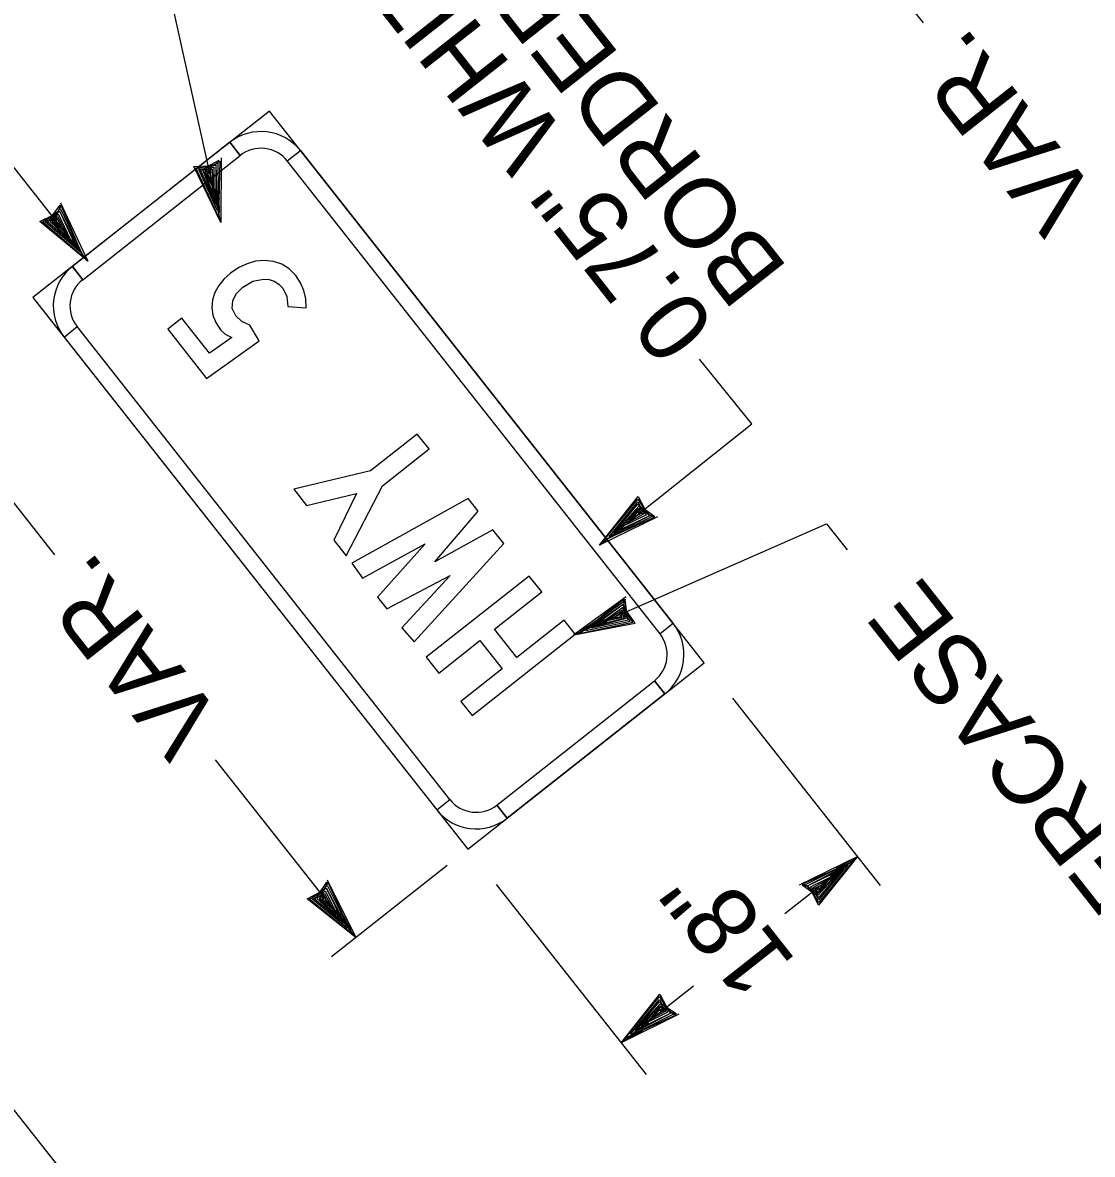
# Model space of a CAD drawing. Extents: x 671946 to 673995, y 1673066 to 1674936.
# Drawn here: x 672428.5 to 672492.5, y 1673764.1 to 1673831.7 of the extents above; entities that cross this region are included whole.
import ezdxf

# ---------------------------------------------------------------- set-up
doc = ezdxf.new("R2010")
doc.units = 0
for name, color, linetype in [('C-ANNO-SYMB', 7, 'Continuous'), ('Level 1', 7, 'Continuous'), ('V-SIGNAL-LOOP', 7, 'Continuous')]:
    doc.layers.add(name, color=color, linetype=linetype)

msp = doc.modelspace()

# ---------------------------------------------------------------- linework, layer by layer
at = {"layer": 'C-ANNO-SYMB'}
for p, q in [((672443.297, 1673826.427), (672429.161, 1673815.283)), ((672469.299, 1673793.444), (672443.297, 1673826.427)), ((672440.941, 1673824.57), (672431.517, 1673817.141)), ((672440.941, 1673824.57), (672441.56, 1673823.785)), ((672441.56, 1673823.785), (672440.941, 1673824.57)), ((672432.136, 1673816.355), (672441.56, 1673823.785)), ((672441.56, 1673823.785), (672441.56, 1673823.785)), ((672441.56, 1673823.785), (672441.56, 1673823.785)), ((672444.369, 1673823.452), (672445.154, 1673824.071)), ((672444.369, 1673823.452), (672445.154, 1673824.071)), ((672444.369, 1673823.452), (672445.154, 1673824.071)), ((672445.154, 1673824.071), (672467.442, 1673795.8)), ((672466.657, 1673795.181), (672444.369, 1673823.452)), ((672432.136, 1673816.355), (672431.517, 1673817.141)), ((672431.517, 1673817.141), (672432.136, 1673816.355)), ((672429.161, 1673815.283), (672455.164, 1673782.3)), ((672431.019, 1673812.928), (672431.804, 1673813.547)), ((672431.019, 1673812.928), (672431.804, 1673813.547)), ((672431.804, 1673813.547), (672431.804, 1673813.547)), ((672431.804, 1673813.547), (672431.804, 1673813.547)), ((672454.092, 1673785.275), (672431.804, 1673813.547)), ((672431.019, 1673812.928), (672453.306, 1673784.656)), ((672467.442, 1673795.8), (672466.657, 1673795.181)), ((672467.442, 1673795.8), (672466.657, 1673795.181)), ((672466.657, 1673795.181), (672466.657, 1673795.181)), ((672466.657, 1673795.181), (672466.657, 1673795.181)), ((672455.164, 1673782.3), (672469.299, 1673793.444)), ((672469.299, 1673793.444), (672469.299, 1673793.444)), ((672469.299, 1673793.444), (672469.299, 1673793.444)), ((672456.9, 1673784.943), (672466.324, 1673792.372)), ((672466.324, 1673792.372), (672466.943, 1673791.587)), ((672466.943, 1673791.587), (672466.324, 1673792.372)), ((672466.943, 1673791.587), (672457.52, 1673784.158)), ((672453.306, 1673784.656), (672454.092, 1673785.275)), ((672453.306, 1673784.656), (672454.092, 1673785.275)), ((672457.52, 1673784.158), (672456.9, 1673784.943)), ((672456.9, 1673784.943), (672456.9, 1673784.943)), ((672456.9, 1673784.943), (672456.9, 1673784.943)), ((672456.9, 1673784.943), (672457.52, 1673784.158)), ((672457.52, 1673784.158), (672456.9, 1673784.943))]:
    msp.add_line(p, q, dxfattribs=at)
for points in [[(672469.462, 1673714.173), (672348.811, 1673867.215), (672334.833, 1673856.196), (672455.485, 1673703.154)], [(672445.506, 1673814.671), (672445.473, 1673815.211), (672445.355, 1673815.711), (672445.155, 1673816.172), (672444.873, 1673816.599), (672444.487, 1673816.999), (672444.048, 1673817.283), (672443.554, 1673817.451), (672443.002, 1673817.502), (672442.478, 1673817.453), (672441.966, 1673817.31), (672441.469, 1673817.075), (672440.982, 1673816.745), (672440.584, 1673816.385), (672440.269, 1673815.999), (672440.043, 1673815.592), (672439.903, 1673815.159), (672439.861, 1673814.692), (672439.922, 1673814.238), (672440.096, 1673813.793), (672440.373, 1673813.364), (672440.66, 1673813.1), (672441.059, 1673812.897), (672439.722, 1673811.953), (672438.065, 1673814.054), (672437.22, 1673813.387), (672439.532, 1673810.454), (672442.695, 1673812.705), (672442.133, 1673813.643), (672441.66, 1673813.851), (672441.29, 1673814.188), (672441.076, 1673814.637), (672441.112, 1673815.116), (672441.336, 1673815.524), (672441.714, 1673815.902), (672442.319, 1673816.26), (672442.94, 1673816.394), (672443.279, 1673816.371), (672443.582, 1673816.27), (672443.859, 1673816.094), (672444.101, 1673815.84), (672444.347, 1673815.354), (672444.399, 1673814.756)], [(672445.517, 1673802.862), (672448.518, 1673803.564), (672447.15, 1673800.79), (672447.894, 1673799.847), (672450.054, 1673804.038), (672452.846, 1673806.239), (672452.145, 1673807.128), (672449.353, 1673804.927), (672444.759, 1673803.824)], [(672457.309, 1673800.577), (672456.66, 1673801.4), (672453.191, 1673799.485), (672455.785, 1673802.511), (672455.185, 1673803.271), (672448.234, 1673799.416), (672448.867, 1673798.508), (672452.61, 1673800.571), (672449.769, 1673797.364), (672450.317, 1673796.669), (672454.113, 1673798.664), (672451.214, 1673795.531), (672451.955, 1673794.695)], [(672461.584, 1673795.155), (672460.917, 1673796), (672458.09, 1673793.771), (672456.756, 1673795.463), (672459.584, 1673797.692), (672458.841, 1673798.634), (672452.68, 1673793.776), (672453.422, 1673792.834), (672455.893, 1673794.782), (672457.227, 1673793.091), (672454.756, 1673791.143), (672455.422, 1673790.298)]]:
    msp.add_lwpolyline(points, close=True, dxfattribs=at)
for centre, radius, start, end in [((672442.798, 1673822.214), 3, 38.2506, 128.25081), ((672442.798, 1673822.214), 2, 38.2506, 128.25081), ((672433.375, 1673814.785), 3, 128.25054, 218.25075), ((672433.375, 1673814.785), 2, 128.25054, 218.25075), ((672465.086, 1673793.943), 3, 308.25039, 38.2506), ((672465.086, 1673793.943), 2, 308.25039, 38.2506), ((672455.662, 1673786.514), 2, 218.25075, 308.25039), ((672455.662, 1673786.514), 3, 218.25075, 308.25039)]:
    msp.add_arc(centre, radius, start, end, dxfattribs=at)
at = {"layer": 'Level 1'}
for p, q in [((672482.408, 1673831.709), (672447.972, 1673875.39)), ((672432.439, 1673817.458), (672422.781, 1673829.709)), ((672438.785, 1673823.132), (672439.64, 1673823.153)), ((672440.387, 1673819.773), (672438.785, 1673823.132)), ((672438.911, 1673823.051), (672439.568, 1673823.11)), ((672439.18, 1673822.919), (672440.106, 1673823.226)), ((672439.318, 1673822.897), (672439.975, 1673823.09)), ((672439.355, 1673822.985), (672440.106, 1673823.226)), ((672439.568, 1673823.11), (672440.287, 1673823.507)), ((672439.64, 1673823.153), (672440.024, 1673823.235)), ((672439.975, 1673823.09), (672439.986, 1673821.406)), ((672440.024, 1673823.235), (672440.33, 1673823.436)), ((672440.106, 1673823.226), (672440.102, 1673820.868)), ((672440.106, 1673823.226), (672440.182, 1673820.749)), ((672440.134, 1673823.338), (672440.223, 1673823.303)), ((672440.223, 1673823.303), (672440.26, 1673820.124)), ((672440.33, 1673823.436), (672440.248, 1673820.309)), ((672440.422, 1673823.631), (672440.387, 1673819.773)), ((672440.27, 1673820.072), (672438.911, 1673823.051)), ((672439.061, 1673822.975), (672439.355, 1673822.985)), ((672440.176, 1673820.509), (672439.061, 1673822.975)), ((672440.102, 1673820.868), (672439.18, 1673822.919)), ((672440.182, 1673820.749), (672439.318, 1673822.897)), ((672439.424, 1673822.785), (672439.868, 1673822.962)), ((672439.986, 1673821.406), (672439.424, 1673822.785)), ((672439.846, 1673823.062), (672439.438, 1673822.843)), ((672439.438, 1673822.843), (672439.899, 1673822.056)), ((672439.523, 1673822.697), (672439.777, 1673822.887)), ((672439.913, 1673821.872), (672439.523, 1673822.697)), ((672439.605, 1673822.691), (672439.7, 1673822.736)), ((672439.794, 1673822.303), (672439.605, 1673822.691)), ((672439.7, 1673822.736), (672439.846, 1673823.062)), ((672439.777, 1673822.887), (672439.794, 1673822.303)), ((672439.868, 1673822.962), (672439.913, 1673821.872)), ((672439.899, 1673822.056), (672439.879, 1673821.785)), ((672439.879, 1673821.785), (672440.034, 1673821.307)), ((672440.034, 1673821.307), (672440.037, 1673821.79)), ((672440.291, 1673821.228), (672440.176, 1673820.509)), ((672440.324, 1673820.323), (672440.291, 1673821.228)), ((672430.027, 1673819.81), (672430.74, 1673820.476)), ((672430.159, 1673819.944), (672430.74, 1673820.476)), ((672430.3, 1673820.147), (672430.787, 1673820.807)), ((672430.347, 1673820.215), (672430.662, 1673820.45)), ((672430.662, 1673820.45), (672430.856, 1673820.761)), ((672430.787, 1673820.807), (672430.719, 1673820.59)), ((672430.719, 1673820.59), (672430.814, 1673820.596)), ((672430.74, 1673820.476), (672431.722, 1673818.332)), ((672430.74, 1673820.476), (672431.844, 1673818.258)), ((672430.808, 1673820.954), (672432.439, 1673817.458)), ((672430.814, 1673820.596), (672432.177, 1673817.723)), ((672430.856, 1673820.761), (672432.089, 1673817.886)), ((672429.579, 1673819.839), (672430.347, 1673820.215)), ((672432.439, 1673817.458), (672429.579, 1673819.839)), ((672429.728, 1673819.818), (672430.3, 1673820.147)), ((672432.208, 1673817.68), (672429.728, 1673819.818)), ((672429.896, 1673819.811), (672430.159, 1673819.944)), ((672431.94, 1673818.037), (672429.896, 1673819.811)), ((672431.722, 1673818.332), (672430.027, 1673819.81)), ((672430.162, 1673819.849), (672430.677, 1673820.299)), ((672431.844, 1673818.258), (672430.162, 1673819.849)), ((672430.572, 1673820.219), (672430.294, 1673819.849)), ((672430.294, 1673819.849), (672431.041, 1673819.327)), ((672430.305, 1673819.79), (672430.634, 1673820.137)), ((672431.392, 1673818.773), (672430.305, 1673819.79)), ((672430.431, 1673819.752), (672430.583, 1673820.031)), ((672431.131, 1673819.166), (672430.431, 1673819.752)), ((672430.509, 1673819.781), (672430.576, 1673819.862)), ((672430.843, 1673819.508), (672430.509, 1673819.781)), ((672430.576, 1673819.862), (672430.572, 1673820.219)), ((672430.583, 1673820.031), (672430.843, 1673819.508)), ((672430.634, 1673820.137), (672431.131, 1673819.166)), ((672430.677, 1673820.299), (672431.392, 1673818.773)), ((672431.041, 1673819.327), (672431.136, 1673819.072)), ((672430.479, 1673799.898), (672422.501, 1673810.019)), ((672463.039, 1673800.478), (672465.359, 1673803.388)), ((672463.257, 1673800.714), (672465.34, 1673803.239)), ((672463.608, 1673800.99), (672465.338, 1673803.071)), ((672463.827, 1673801.09), (672465.381, 1673802.806)), ((672463.898, 1673801.213), (672465.339, 1673802.939)), ((672465.338, 1673803.071), (672465.476, 1673802.811)), ((672465.339, 1673802.939), (672466.02, 1673802.241)), ((672465.34, 1673803.239), (672465.682, 1673802.674)), ((672465.359, 1673803.388), (672465.751, 1673802.628)), ((672465.381, 1673802.806), (672465.841, 1673802.3)), ((672465.476, 1673802.811), (672466.02, 1673802.241)), ((672466.499, 1673802.183), (672463.039, 1673800.478)), ((672466.142, 1673802.169), (672463.299, 1673800.745)), ((672466.307, 1673802.131), (672463.459, 1673800.837)), ((672466.02, 1673802.241), (672463.827, 1673801.09)), ((672466.02, 1673802.241), (672463.898, 1673801.213)), ((672464.332, 1673801.553), (672465.325, 1673802.661)), ((672465.841, 1673802.3), (672464.332, 1673801.553)), ((672464.719, 1673801.822), (672465.29, 1673802.534)), ((672465.679, 1673802.339), (672464.719, 1673801.822)), ((672465.384, 1673802.674), (672464.878, 1673801.916)), ((672465.054, 1673802.117), (672465.32, 1673802.457)), ((672465.571, 1673802.389), (672465.054, 1673802.117)), ((672465.29, 1673802.534), (672465.571, 1673802.389)), ((672465.32, 1673802.457), (672465.402, 1673802.392)), ((672465.325, 1673802.661), (672465.679, 1673802.339)), ((672465.76, 1673802.403), (672465.384, 1673802.674)), ((672465.402, 1673802.392), (672465.76, 1673802.403)), ((672465.682, 1673802.674), (672466.352, 1673802.201)), ((672465.751, 1673802.628), (672465.993, 1673802.319)), ((672465.993, 1673802.319), (672466.307, 1673802.131)), ((672466.352, 1673802.201), (672466.133, 1673802.265)), ((672466.133, 1673802.265), (672466.142, 1673802.169)), ((672464.878, 1673801.916), (672464.625, 1673801.815)), ((672464.628, 1673797.388), (672461.509, 1673795.119)), ((672464.449, 1673797.078), (672461.866, 1673795.224)), ((672464.493, 1673797.243), (672462.023, 1673795.323)), ((672464.457, 1673796.937), (672462.417, 1673795.531)), ((672464.457, 1673796.937), (672462.559, 1673795.537)), ((672464.425, 1673796.752), (672463.062, 1673795.763)), ((672464.659, 1673796.108), (672464.425, 1673796.752)), ((672464.53, 1673797.026), (672464.449, 1673797.078)), ((672464.708, 1673796.19), (672464.457, 1673796.937)), ((672464.758, 1673796.01), (672464.457, 1673796.937)), ((672464.513, 1673796.877), (672464.493, 1673797.243)), ((672464.674, 1673796.519), (672464.513, 1673796.877)), ((672464.576, 1673797.25), (672464.53, 1673797.026)), ((672464.682, 1673796.436), (672464.576, 1673797.25)), ((672462.417, 1673795.531), (672464.659, 1673796.108)), ((672462.954, 1673795.743), (672463.341, 1673796.031)), ((672463.062, 1673795.763), (672464.505, 1673796.127)), ((672463.637, 1673796.078), (672463.43, 1673795.9)), ((672464.385, 1673796.589), (672463.48, 1673795.98)), ((672463.48, 1673795.98), (672464.376, 1673796.155)), ((672464.544, 1673796.173), (672463.637, 1673796.078)), ((672464.378, 1673796.471), (672463.898, 1673796.14)), ((672463.898, 1673796.14), (672464.322, 1673796.217)), ((672464.303, 1673796.32), (672464.479, 1673796.631)), ((672464.322, 1673796.217), (672464.303, 1673796.32)), ((672464.376, 1673796.155), (672464.378, 1673796.471)), ((672464.505, 1673796.127), (672464.385, 1673796.589)), ((672464.479, 1673796.631), (672464.544, 1673796.173)), ((672465.164, 1673795.818), (672464.674, 1673796.519)), ((672465.024, 1673795.871), (672464.682, 1673796.436)), ((672464.873, 1673795.947), (672464.708, 1673796.19)), ((672461.509, 1673795.119), (672465.164, 1673795.818)), ((672461.819, 1673795.201), (672465.024, 1673795.871)), ((672461.866, 1673795.224), (672461.989, 1673795.394)), ((672461.989, 1673795.394), (672462.737, 1673795.903)), ((672462.226, 1673795.384), (672464.873, 1673795.947)), ((672462.737, 1673795.903), (672462.226, 1673795.384)), ((672462.559, 1673795.537), (672464.758, 1673796.01)), ((672463.43, 1673795.9), (672462.954, 1673795.743)), ((672462.023, 1673795.323), (672461.819, 1673795.201)), ((672471.001, 1673791.34), (672479.83, 1673780.141)), ((672448.463, 1673777.018), (672440.083, 1673787.647)), ((672474.123, 1673778.454), (672478.463, 1673781.876)), ((672475.001, 1673780.172), (672478.463, 1673781.876)), ((672478.463, 1673781.876), (672476.141, 1673778.967)), ((672453.923, 1673781.322), (672447.018, 1673775.879)), ((672475.193, 1673780.224), (672478.042, 1673781.516)), ((672475.359, 1673780.186), (672478.203, 1673781.608)), ((672475.48, 1673780.114), (672477.675, 1673781.264)), ((672475.48, 1673780.114), (672477.603, 1673781.141)), ((672477.675, 1673781.264), (672476.119, 1673779.549)), ((672478.245, 1673781.64), (672476.159, 1673779.116)), ((672477.603, 1673781.141), (672476.161, 1673779.415)), ((672477.893, 1673781.364), (672476.162, 1673779.284)), ((672477.995, 1673781.579), (672477.196, 1673781.154)), ((672477.196, 1673781.154), (672477.893, 1673781.364)), ((672478.203, 1673781.608), (672477.995, 1673781.579)), ((672478.042, 1673781.516), (672478.245, 1673781.64)), ((672446.759, 1673780.479), (672448.463, 1673777.018)), ((672475.659, 1673780.055), (672477.169, 1673780.801)), ((672475.822, 1673780.016), (672476.782, 1673780.532)), ((672477.169, 1673780.801), (672476.175, 1673779.693)), ((672476.782, 1673780.532), (672476.21, 1673779.821)), ((672476.622, 1673780.439), (672476.876, 1673780.539)), ((672477.237, 1673780.887), (672476.802, 1673780.679)), ((672476.876, 1673780.539), (672477.237, 1673780.887)), ((672446.002, 1673779.32), (672446.701, 1673780)), ((672446.131, 1673779.456), (672446.701, 1673780)), ((672446.136, 1673779.361), (672446.642, 1673779.821)), ((672446.268, 1673779.662), (672446.741, 1673780.332)), ((672446.314, 1673779.731), (672446.623, 1673779.973)), ((672446.623, 1673779.973), (672446.811, 1673780.287)), ((672446.642, 1673779.821), (672447.388, 1673778.311)), ((672446.741, 1673780.332), (672446.677, 1673780.113)), ((672446.677, 1673780.113), (672446.773, 1673780.121)), ((672446.701, 1673780), (672447.728, 1673777.877)), ((672446.701, 1673780), (672447.851, 1673777.806)), ((672446.773, 1673780.121), (672448.195, 1673777.277)), ((672446.811, 1673780.287), (672448.103, 1673777.438)), ((672456.866, 1673780.196), (672465.821, 1673768.836)), ((672475.819, 1673779.681), (672475.148, 1673780.154)), ((672475.148, 1673780.154), (672475.367, 1673780.091)), ((672475.508, 1673780.036), (672475.193, 1673780.224)), ((672475.367, 1673780.091), (672475.359, 1673780.186)), ((672476.024, 1673779.544), (672475.48, 1673780.114)), ((672476.161, 1673779.415), (672475.48, 1673780.114)), ((672475.749, 1673779.727), (672475.508, 1673780.036)), ((672476.119, 1673779.549), (672475.659, 1673780.055)), ((672476.098, 1673779.963), (672475.741, 1673779.952)), ((672475.741, 1673779.952), (672476.116, 1673779.681)), ((672476.175, 1673779.693), (672475.822, 1673780.016)), ((672475.929, 1673779.966), (672476.446, 1673780.237)), ((672476.21, 1673779.821), (672475.929, 1673779.966)), ((672476.18, 1673779.897), (672476.098, 1673779.963)), ((672476.116, 1673779.681), (672476.622, 1673780.439)), ((672476.446, 1673780.237), (672476.18, 1673779.897)), ((672445.554, 1673779.339), (672446.314, 1673779.731)), ((672448.463, 1673777.018), (672445.554, 1673779.339)), ((672445.702, 1673779.321), (672446.268, 1673779.662)), ((672448.227, 1673777.235), (672445.702, 1673779.321)), ((672445.871, 1673779.318), (672446.131, 1673779.456)), ((672447.951, 1673777.587), (672445.871, 1673779.318)), ((672447.728, 1673777.877), (672446.002, 1673779.32)), ((672447.851, 1673777.806), (672446.136, 1673779.361)), ((672446.539, 1673779.74), (672446.268, 1673779.364)), ((672446.268, 1673779.364), (672447.026, 1673778.858)), ((672446.28, 1673779.305), (672446.603, 1673779.659)), ((672447.388, 1673778.311), (672446.28, 1673779.305)), ((672446.407, 1673779.27), (672446.553, 1673779.551)), ((672447.119, 1673778.698), (672446.407, 1673779.27)), ((672446.484, 1673779.3), (672446.55, 1673779.382)), ((672446.824, 1673779.034), (672446.484, 1673779.3)), ((672446.55, 1673779.382), (672446.539, 1673779.74)), ((672446.553, 1673779.551), (672446.824, 1673779.034)), ((672446.603, 1673779.659), (672447.119, 1673778.698)), ((672476.141, 1673778.967), (672475.749, 1673779.727)), ((672476.159, 1673779.116), (672475.819, 1673779.681)), ((672476.162, 1673779.284), (672476.024, 1673779.544)), ((672447.026, 1673778.858), (672447.126, 1673778.605)), ((672447.126, 1673778.605), (672447.474, 1673778.243)), ((672447.474, 1673778.243), (672447.266, 1673778.679)), ((672448.166, 1673777.485), (672447.741, 1673778.284)), ((672447.741, 1673778.284), (672447.951, 1673777.587)), ((672448.103, 1673777.438), (672448.227, 1673777.235)), ((672448.195, 1673777.277), (672448.166, 1673777.485)), ((672464.327, 1673770.732), (672468.652, 1673774.142)), ((672464.327, 1673770.732), (672466.648, 1673773.641)), ((672464.545, 1673770.968), (672466.63, 1673773.492)), ((672464.896, 1673771.243), (672466.627, 1673773.324)), ((672465.115, 1673771.343), (672466.67, 1673773.058)), ((672465.187, 1673771.467), (672466.629, 1673773.192)), ((672466.627, 1673773.324), (672466.765, 1673773.063)), ((672466.629, 1673773.192), (672467.31, 1673772.494)), ((672466.63, 1673773.492), (672466.971, 1673772.927)), ((672466.648, 1673773.641), (672467.041, 1673772.881)), ((672466.67, 1673773.058), (672467.131, 1673772.552)), ((672466.765, 1673773.063), (672467.31, 1673772.494)), ((672467.789, 1673772.435), (672464.327, 1673770.732)), ((672467.431, 1673772.421), (672464.587, 1673771)), ((672467.596, 1673772.383), (672464.748, 1673771.091)), ((672467.31, 1673772.494), (672465.115, 1673771.343)), ((672467.31, 1673772.494), (672465.187, 1673771.467)), ((672465.62, 1673771.806), (672466.615, 1673772.914)), ((672467.131, 1673772.552), (672465.62, 1673771.806)), ((672466.008, 1673772.075), (672466.579, 1673772.787)), ((672466.968, 1673772.592), (672466.008, 1673772.075)), ((672466.673, 1673772.927), (672466.167, 1673772.169)), ((672466.343, 1673772.37), (672466.609, 1673772.71)), ((672466.861, 1673772.641), (672466.343, 1673772.37)), ((672466.579, 1673772.787), (672466.861, 1673772.641)), ((672466.609, 1673772.71), (672466.692, 1673772.645)), ((672466.615, 1673772.914), (672466.968, 1673772.592)), ((672467.049, 1673772.656), (672466.673, 1673772.927)), ((672466.692, 1673772.645), (672467.049, 1673772.656)), ((672466.971, 1673772.927), (672467.642, 1673772.454)), ((672467.041, 1673772.881), (672467.282, 1673772.571)), ((672467.282, 1673772.571), (672467.596, 1673772.383)), ((672467.642, 1673772.454), (672467.422, 1673772.517)), ((672467.422, 1673772.517), (672467.431, 1673772.421)), ((672465.914, 1673772.068), (672465.553, 1673771.72)), ((672465.553, 1673771.72), (672465.988, 1673771.928)), ((672466.167, 1673772.169), (672465.914, 1673772.068)), ((672464.748, 1673771.091), (672464.545, 1673770.968)), ((672464.587, 1673771), (672464.794, 1673771.029)), ((672464.794, 1673771.029), (672465.594, 1673771.454)), ((672465.594, 1673771.454), (672464.896, 1673771.243))]:
    msp.add_line(p, q, dxfattribs=at)
for points in [[(672440.387, 1673819.773), (672435.68, 1673841.052), (672432.935, 1673844.535)], [(672463.039, 1673800.478), (672472.152, 1673807.738), (672469.014, 1673811.594)], [(672461.509, 1673795.119), (672476.617, 1673801.756), (672477.839, 1673800.205)]]:
    msp.add_lwpolyline(points, dxfattribs=at)
at = {"layer": 'V-SIGNAL-LOOP'}
msp.add_lwpolyline([(672473.016, 1673800.576), (672473.016, 1673800.576), (672473.016, 1673800.576)], dxfattribs=at)

# ---------------------------------------------------------------- texts
at = {"layer": 'Level 1'}
for s, p in [('BORDER STRIP', (672474.378, 1673816.991)), ('0.75" WHITE ', (672470.084, 1673813.606)), ('VAR.', (672492.961, 1673821.303)), ('VAR.', (672440.656, 1673789.97)), ('8" UPPERCASE', (672507.761, 1673766.257)), ('18"', (672474.871, 1673775.57))]:
    msp.add_text(s, height=4.2, rotation=128.25054, dxfattribs=at).set_placement(p)

doc.saveas('drawing.dxf')
